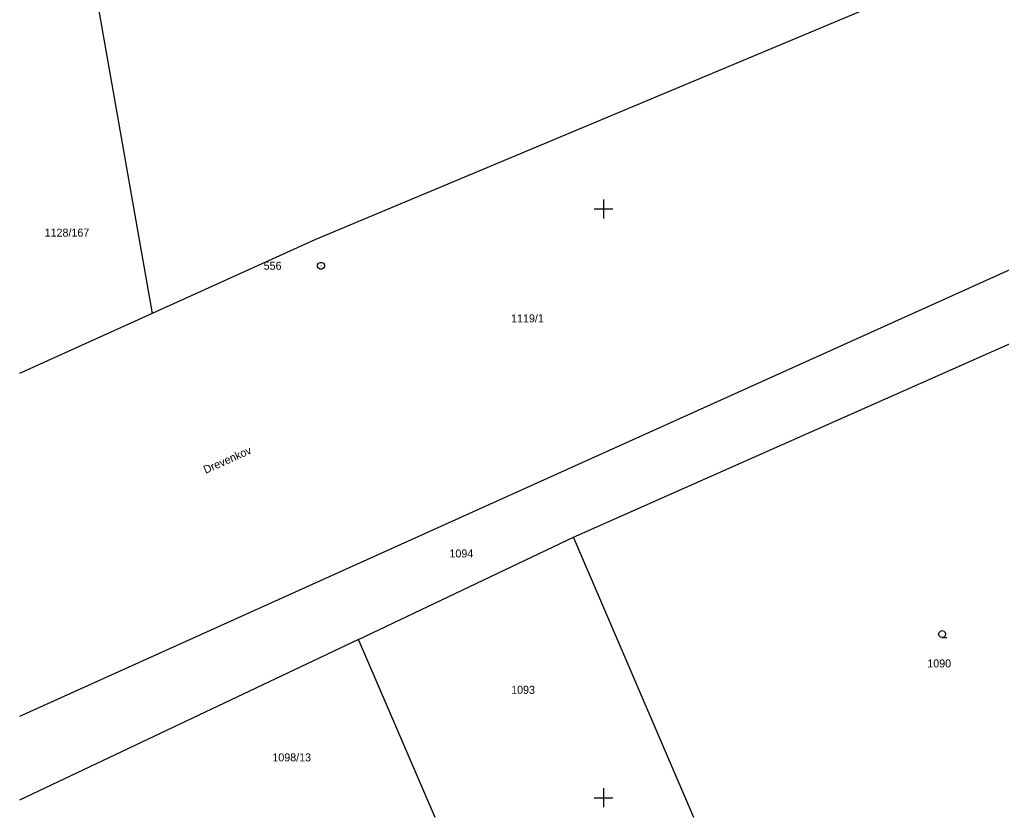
# Model space of a CAD drawing. Extents: x -772300 to -772183, y -1034101 to -1034019.
# Drawn here: x -772299.81 to -772258.1, y -1034100.83 to -1034066.96 of the extents above; entities that cross this region are included whole.
import ezdxf

# ---------------------------------------------------------------- set-up
doc = ezdxf.new("R2010")
doc.units = 0
for name, color, linetype in [('KM_body', 7, 'Continuous'), ('KM_hranice', 7, 'Continuous'), ('KM_mezni_znaky', 7, 'Continuous'), ('KM_parcelni_cisla', 7, 'Continuous'), ('KM_popis', 7, 'Continuous'), ('souradnicova_sit', 7, 'Continuous')]:
    doc.layers.add(name, color=color, linetype=linetype)

msp = doc.modelspace()

# ---------------------------------------------------------------- linework, layer by layer
at = {"layer": 'KM_body'}
msp.add_lwpolyline([(-772260.61, -1034093.2), (-772260.686, -1034093.18), (-772260.74, -1034093.126), (-772260.76, -1034093.052), (-772260.74, -1034092.978), (-772260.686, -1034092.924), (-772260.612, -1034092.904), (-772260.538, -1034092.924), (-772260.484, -1034092.978), (-772260.464, -1034093.054), (-772260.484, -1034093.13), (-772260.538, -1034093.184), (-772260.614, -1034093.204), (-772260.414, -1034093.204)], dxfattribs=at)
at = {"layer": 'KM_hranice'}
for p, q in [((-772299.808, -1034047.448), (-772294.17, -1034079.44)), ((-772262.97, -1034066.14), (-772287.27, -1034076.31)), ((-772237.52, -1034068.47), (-772299.808, -1034096.549)), ((-772276.27, -1034088.94), (-772240.68, -1034073.14)), ((-772287.27, -1034076.31), (-772294.17, -1034079.44)), ((-772294.17, -1034079.44), (-772299.808, -1034081.993)), ((-772285.41, -1034093.28), (-772276.27, -1034088.94)), ((-772271.169, -1034100.835), (-772276.27, -1034088.94)), ((-772285.41, -1034093.28), (-772299.808, -1034100.106)), ((-772282.155, -1034100.835), (-772285.41, -1034093.28))]:
    msp.add_line(p, q, dxfattribs=at)
at = {"layer": 'KM_mezni_znaky'}
msp.add_line((-772287.01, -1034077.41), (-772286.99, -1034077.41), dxfattribs=at)
msp.add_lwpolyline([(-772286.962, -1034077.266), (-772286.894, -1034077.304), (-772286.856, -1034077.372), (-772286.856, -1034077.45), (-772286.894, -1034077.518), (-772286.962, -1034077.556), (-772287.04, -1034077.556), (-772287.108, -1034077.518), (-772287.146, -1034077.45), (-772287.146, -1034077.372), (-772287.108, -1034077.304), (-772287.04, -1034077.266)], close=True, dxfattribs=at)
at = {"layer": 'souradnicova_sit'}
for p, q in [((-772275, -1034074.6), (-772275, -1034075.4)), ((-772275.4, -1034075), (-772274.6, -1034075)), ((-772275, -1034099.6), (-772275, -1034100.4)), ((-772275.4, -1034100), (-772274.6, -1034100))]:
    msp.add_line(p, q, dxfattribs=at)

# ---------------------------------------------------------------- texts
at = {"layer": 'KM_mezni_znaky'}
msp.add_text('556', height=0.34, dxfattribs=at).set_placement((-772289.439, -1034077.58))
at = {"layer": 'KM_parcelni_cisla'}
for s, p in [('1128/167', (-772298.745, -1034076.174)), ('1119/1', (-772278.926, -1034079.815)), ('1094', (-772281.546, -1034089.798)), ('1090', (-772261.242, -1034094.467)), ('1093', (-772278.923, -1034095.588)), ('1098/13', (-772289.069, -1034098.458))]:
    msp.add_text(s, height=0.34, dxfattribs=at).set_placement(p)
at = {"layer": 'KM_popis'}
msp.add_text('Drevenkov', height=0.34, rotation=23.9496, dxfattribs=at).set_placement((-772291.907, -1034086.251))

doc.saveas('drawing.dxf')
